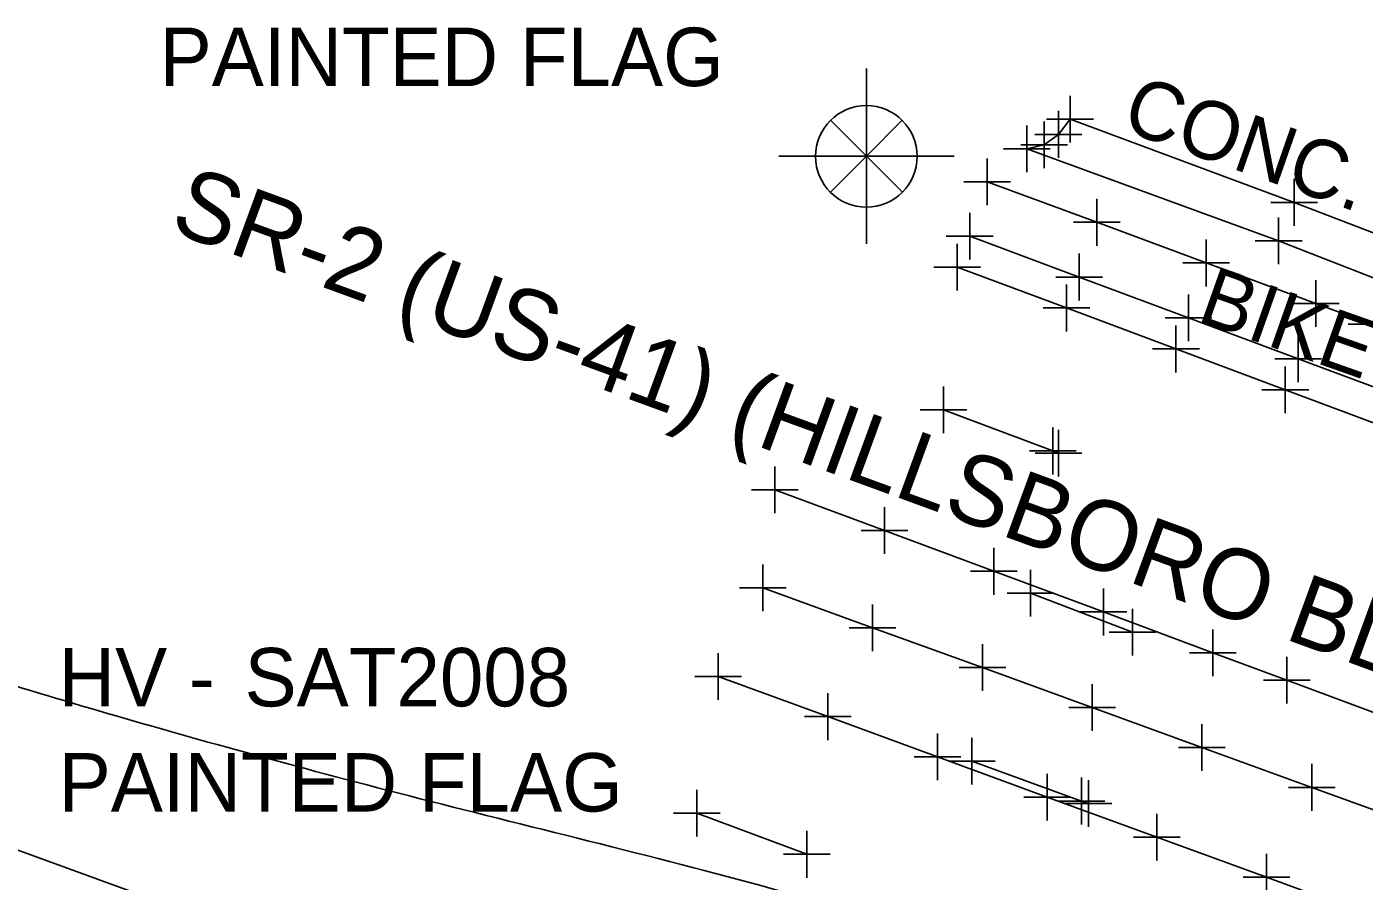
# Model space of a CAD drawing. Extents: x 0 to 1944463, y 0 to 420651.
# Drawn here: x 1942403.1 to 1942517.6, y 417930.2 to 418003.4 of the extents above; entities that cross this region are included whole.
import ezdxf

# ---------------------------------------------------------------- set-up
doc = ezdxf.new("R2010")
doc.units = 0
for name, color, linetype in [('AERIAL - CTRL - Points', 7, 'Continuous'), ('AERIAL - CTRL - Text', 7, 'Continuous'), ('SUR - DRG - Storm Sewer Text', 7, 'Continuous'), ('SUR - DTM - Breaklines', 7, 'Continuous'), ('SUR - DTM - Breaklines - Points - Locators', 7, 'Continuous'), ('SUR - TR-CTRL - Pavement Marking', 7, 'Continuous'), ('SUR - TR-CTRL - Pavement Marking - Points - Locators', 7, 'Continuous'), ('SUR - TRAN - Features', 7, 'Continuous'), ('SUR - TRAN - Features - Points - Locators', 7, 'Continuous'), ('SUR - TRAN - Features Text', 7, 'Continuous'), ('SUR - TRAN - Roads Text', 7, 'Continuous')]:
    doc.layers.add(name, color=color, linetype=linetype)

msp = doc.modelspace()

# ---------------------------------------------------------------- linework, layer by layer
at = {"layer": 'AERIAL - CTRL - Points'}
for p, q in [((1942474.94, 417992.29), (1942474.94, 417999.79)), ((1942474.94, 417992.29), (1942471.87, 417995.36)), ((1942474.94, 417992.29), (1942478.01, 417995.36)), ((1942467.44, 417992.29), (1942474.94, 417992.29)), ((1942471.86, 417989.21), (1942474.94, 417992.29)), ((1942474.94, 417992.29), (1942474.94, 417992.29)), ((1942474.94, 417992.29), (1942482.44, 417992.29)), ((1942478.03, 417989.21), (1942474.94, 417992.29)), ((1942474.94, 417984.79), (1942474.94, 417992.29))]:
    msp.add_line(p, q, dxfattribs=at)
msp.add_circle((1942474.94, 417992.27), 4.35, dxfattribs=at)
at = {"layer": 'SUR - DRG - Storm Sewer Text'}
msp.add_open_spline([(1942357.56, 417966.03), (1942368.77, 417953.91), (1942538.56, 417912.18), (1942553.38, 417877.57)], degree=2, dxfattribs=at)
at = {"layer": 'SUR - DTM - Breaklines'}
msp.add_lwpolyline([(1942466.07, 417955.35), (1942475.47, 417951.93), (1942484.87, 417948.52), (1942494.27, 417945.1), (1942503.66, 417941.68), (1942513.06, 417938.27), (1942522.46, 417934.85)], dxfattribs=at)
at = {"layer": 'SUR - DTM - Breaklines - Points - Locators'}
for p, q in [((1942466.07, 417955.35), (1942466.07, 417957.35)), ((1942466.07, 417955.35), (1942464.07, 417955.35)), ((1942466.07, 417955.35), (1942468.07, 417955.35)), ((1942466.07, 417955.35), (1942466.07, 417953.35)), ((1942475.47, 417951.93), (1942475.47, 417953.93)), ((1942475.47, 417951.93), (1942473.47, 417951.93)), ((1942475.47, 417951.93), (1942477.47, 417951.93)), ((1942475.47, 417951.93), (1942475.47, 417949.93)), ((1942484.87, 417948.52), (1942484.87, 417950.52)), ((1942484.87, 417948.52), (1942482.87, 417948.52)), ((1942484.87, 417948.52), (1942486.87, 417948.52)), ((1942484.87, 417948.52), (1942484.87, 417946.52)), ((1942494.27, 417945.1), (1942494.27, 417947.1)), ((1942494.27, 417945.1), (1942492.27, 417945.1)), ((1942494.27, 417945.1), (1942496.27, 417945.1)), ((1942494.27, 417945.1), (1942494.27, 417943.1)), ((1942503.66, 417941.68), (1942503.66, 417943.68)), ((1942503.66, 417941.68), (1942501.66, 417941.68)), ((1942503.66, 417941.68), (1942505.66, 417941.68)), ((1942503.66, 417941.68), (1942503.66, 417939.68)), ((1942513.06, 417938.27), (1942513.06, 417940.27)), ((1942513.06, 417938.27), (1942511.06, 417938.27)), ((1942513.06, 417938.27), (1942515.06, 417938.27)), ((1942513.06, 417938.27), (1942513.06, 417936.27))]:
    msp.add_line(p, q, dxfattribs=at)
at = {"layer": 'SUR - TR-CTRL - Pavement Marking'}
for points in [[(1942485.28, 417990.1), (1942494.66, 417986.63), (1942504.03, 417983.15), (1942513.41, 417979.68), (1942518.19, 417977.91), (1942527.57, 417974.44), (1942536.95, 417970.96), (1942546.32, 417967.49), (1942554.67, 417964.4), (1942564.05, 417960.92), (1942573.42, 417957.45), (1942582.8, 417953.98), (1942592.18, 417950.5), (1942601.04, 417947.22), (1942610.31, 417943.49), (1942615.47, 417941.42), (1942622.2, 417939.05), (1942629.46, 417936.74), (1942645.59, 417933.58)], [(1942482.7, 417982.8), (1942492.07, 417979.3), (1942501.44, 417975.79), (1942510.8, 417972.29), (1942520.17, 417968.79), (1942529.53, 417965.28), (1942538.9, 417961.78), (1942544.32, 417959.75), (1942553.68, 417956.25), (1942563.05, 417952.75), (1942572.42, 417949.24), (1942581.78, 417945.74), (1942591.15, 417942.24), (1942600.51, 417938.73), (1942609.88, 417935.23), (1942617.64, 417932.33)], [(1942481.55, 417970.58), (1942490.91, 417967.06), (1942491.39, 417966.88)], [(1942467.11, 417963.74), (1942476.48, 417960.25), (1942485.86, 417956.76), (1942495.23, 417953.28), (1942504.6, 417949.79), (1942510.92, 417947.44), (1942520.3, 417943.95)], [(1942488.99, 417954.88), (1942497.72, 417951.56)], [(1942462.25, 417947.75), (1942471.64, 417944.32), (1942481.03, 417940.88), (1942490.42, 417937.44), (1942499.81, 417934.01), (1942509.2, 417930.57), (1942518.59, 417927.13)], [(1942483.96, 417940.52), (1942493.36, 417937.1), (1942493.95, 417936.89)], [(1942460.42, 417936.05), (1942469.83, 417932.54)]]:
    msp.add_lwpolyline(points, dxfattribs=at)
at = {"layer": 'SUR - TR-CTRL - Pavement Marking - Points - Locators'}
for p, q in [((1942485.28, 417990.1), (1942485.28, 417992.1)), ((1942485.28, 417990.1), (1942483.28, 417990.1)), ((1942485.28, 417990.1), (1942487.28, 417990.1)), ((1942485.28, 417990.1), (1942485.28, 417988.1)), ((1942494.66, 417986.63), (1942494.66, 417988.63)), ((1942494.66, 417986.63), (1942492.66, 417986.63)), ((1942494.66, 417986.63), (1942496.66, 417986.63)), ((1942494.66, 417986.63), (1942494.66, 417984.63)), ((1942504.03, 417983.15), (1942504.03, 417985.15)), ((1942482.7, 417982.8), (1942482.7, 417984.8)), ((1942504.03, 417983.15), (1942502.03, 417983.15)), ((1942504.03, 417983.15), (1942506.03, 417983.15)), ((1942504.03, 417983.15), (1942504.03, 417981.15)), ((1942482.7, 417982.8), (1942480.7, 417982.8)), ((1942482.7, 417982.8), (1942484.7, 417982.8)), ((1942482.7, 417982.8), (1942482.7, 417980.8)), ((1942513.41, 417979.68), (1942513.41, 417981.68)), ((1942492.07, 417979.3), (1942492.07, 417981.3)), ((1942513.41, 417979.68), (1942511.41, 417979.68)), ((1942513.41, 417979.68), (1942515.41, 417979.68)), ((1942513.41, 417979.68), (1942513.41, 417977.68)), ((1942492.07, 417979.3), (1942490.07, 417979.3)), ((1942492.07, 417979.3), (1942494.07, 417979.3)), ((1942492.07, 417979.3), (1942492.07, 417977.3)), ((1942501.44, 417975.79), (1942501.44, 417977.79)), ((1942518.19, 417977.91), (1942516.19, 417977.91)), ((1942501.44, 417975.79), (1942499.44, 417975.79)), ((1942501.44, 417975.79), (1942503.44, 417975.79)), ((1942501.44, 417975.79), (1942501.44, 417973.79)), ((1942510.8, 417972.29), (1942510.8, 417974.29)), ((1942481.55, 417970.58), (1942481.55, 417972.58)), ((1942510.8, 417972.29), (1942508.8, 417972.29)), ((1942510.8, 417972.29), (1942512.8, 417972.29)), ((1942510.8, 417972.29), (1942510.8, 417970.29)), ((1942481.55, 417970.58), (1942479.55, 417970.58)), ((1942481.55, 417970.58), (1942483.55, 417970.58)), ((1942481.55, 417970.58), (1942481.55, 417968.58)), ((1942490.91, 417967.06), (1942490.91, 417969.06)), ((1942491.39, 417966.88), (1942491.39, 417968.88)), ((1942490.91, 417967.06), (1942488.91, 417967.06)), ((1942491.39, 417966.88), (1942489.39, 417966.88)), ((1942490.91, 417967.06), (1942492.91, 417967.06)), ((1942490.91, 417967.06), (1942490.91, 417965.06)), ((1942491.39, 417966.88), (1942493.39, 417966.88)), ((1942491.39, 417966.88), (1942491.39, 417964.88)), ((1942467.11, 417963.74), (1942467.11, 417965.74)), ((1942467.11, 417963.74), (1942465.11, 417963.74)), ((1942467.11, 417963.74), (1942469.11, 417963.74)), ((1942467.11, 417963.74), (1942467.11, 417961.74)), ((1942476.48, 417960.25), (1942476.48, 417962.25)), ((1942476.48, 417960.25), (1942474.48, 417960.25)), ((1942476.48, 417960.25), (1942478.48, 417960.25)), ((1942476.48, 417960.25), (1942476.48, 417958.25)), ((1942485.86, 417956.76), (1942485.86, 417958.76)), ((1942485.86, 417956.76), (1942483.86, 417956.76)), ((1942485.86, 417956.76), (1942487.86, 417956.76)), ((1942485.86, 417956.76), (1942485.86, 417954.76)), ((1942488.99, 417954.88), (1942488.99, 417956.88)), ((1942488.99, 417954.88), (1942486.99, 417954.88)), ((1942488.99, 417954.88), (1942490.99, 417954.88)), ((1942488.99, 417954.88), (1942488.99, 417952.88)), ((1942495.23, 417953.28), (1942495.23, 417955.28)), ((1942495.23, 417953.28), (1942493.23, 417953.28)), ((1942495.23, 417953.28), (1942497.23, 417953.28)), ((1942495.23, 417953.28), (1942495.23, 417951.28)), ((1942497.72, 417951.56), (1942497.72, 417953.56)), ((1942497.72, 417951.56), (1942495.72, 417951.56)), ((1942497.72, 417951.56), (1942499.72, 417951.56)), ((1942497.72, 417951.56), (1942497.72, 417949.56)), ((1942504.6, 417949.79), (1942504.6, 417951.79)), ((1942462.25, 417947.75), (1942462.25, 417949.75)), ((1942504.6, 417949.79), (1942502.6, 417949.79)), ((1942504.6, 417949.79), (1942506.6, 417949.79)), ((1942504.6, 417949.79), (1942504.6, 417947.79)), ((1942510.92, 417947.44), (1942510.92, 417949.44)), ((1942462.25, 417947.75), (1942460.25, 417947.75)), ((1942462.25, 417947.75), (1942464.25, 417947.75)), ((1942462.25, 417947.75), (1942462.25, 417945.75)), ((1942510.92, 417947.44), (1942508.92, 417947.44)), ((1942510.92, 417947.44), (1942512.92, 417947.44)), ((1942510.92, 417947.44), (1942510.92, 417945.44)), ((1942471.64, 417944.32), (1942471.64, 417946.32)), ((1942471.64, 417944.32), (1942469.64, 417944.32)), ((1942471.64, 417944.32), (1942473.64, 417944.32)), ((1942471.64, 417944.32), (1942471.64, 417942.32)), ((1942481.03, 417940.88), (1942481.03, 417942.88)), ((1942483.96, 417940.52), (1942483.96, 417942.52)), ((1942481.03, 417940.88), (1942479.03, 417940.88)), ((1942481.03, 417940.88), (1942483.03, 417940.88)), ((1942481.03, 417940.88), (1942481.03, 417938.88)), ((1942483.96, 417940.52), (1942481.96, 417940.52)), ((1942483.96, 417940.52), (1942485.96, 417940.52)), ((1942483.96, 417940.52), (1942483.96, 417938.52)), ((1942490.42, 417937.44), (1942490.42, 417939.44)), ((1942493.36, 417937.1), (1942493.36, 417939.1)), ((1942493.95, 417936.89), (1942493.95, 417938.89)), ((1942460.42, 417936.05), (1942460.42, 417938.05)), ((1942490.42, 417937.44), (1942488.42, 417937.44)), ((1942490.42, 417937.44), (1942492.42, 417937.44)), ((1942490.42, 417937.44), (1942490.42, 417935.44)), ((1942493.36, 417937.1), (1942491.36, 417937.1)), ((1942493.36, 417937.1), (1942495.36, 417937.1)), ((1942493.36, 417937.1), (1942493.36, 417935.1)), ((1942460.42, 417936.05), (1942458.42, 417936.05)), ((1942460.42, 417936.05), (1942462.42, 417936.05)), ((1942460.42, 417936.05), (1942460.42, 417934.05)), ((1942493.95, 417936.89), (1942491.95, 417936.89)), ((1942493.95, 417936.89), (1942495.95, 417936.89)), ((1942493.95, 417936.89), (1942493.95, 417934.89)), ((1942499.81, 417934.01), (1942499.81, 417936.01)), ((1942469.83, 417932.54), (1942469.83, 417934.54)), ((1942499.81, 417934.01), (1942497.81, 417934.01)), ((1942499.81, 417934.01), (1942501.81, 417934.01)), ((1942499.81, 417934.01), (1942499.81, 417932.01)), ((1942469.83, 417932.54), (1942467.83, 417932.54)), ((1942469.83, 417932.54), (1942471.83, 417932.54)), ((1942469.83, 417932.54), (1942469.83, 417930.54)), ((1942509.2, 417930.57), (1942509.2, 417932.57)), ((1942509.2, 417930.57), (1942507.2, 417930.57)), ((1942509.2, 417930.57), (1942511.2, 417930.57)), ((1942509.2, 417930.57), (1942509.2, 417928.57))]:
    msp.add_line(p, q, dxfattribs=at)
at = {"layer": 'SUR - TRAN - Features'}
for points in [[(1942530.76, 417977.1), (1942529.25, 417979.14), (1942528.81, 417981.71), (1942511.56, 417988.34), (1942492.37, 417995.47), (1942491.37, 417994.16), (1942490.15, 417993.26), (1942488.67, 417992.91), (1942510.23, 417985.05), (1942530.49, 417977.15)], [(1942483.78, 417985.45), (1942493.15, 417981.95), (1942502.52, 417978.45), (1942511.89, 417974.95), (1942521.26, 417971.46), (1942525.71, 417969.79), (1942535.08, 417966.29), (1942544.45, 417962.8), (1942553.82, 417959.3), (1942563.19, 417955.8), (1942564.66, 417955.25), (1942574.03, 417951.75), (1942583.4, 417948.25), (1942592.76, 417944.76), (1942602.13, 417941.26), (1942611.5, 417937.76), (1942618.47, 417935.16)], [(1942398.07, 417934.48), (1942398.71, 417933.71), (1942399.31, 417932.17), (1942399.2, 417930.32), (1942396.76, 417924.64), (1942436.93, 417909.73), (1942438.42, 417915.31), (1942439.31, 417916.77), (1942440.73, 417917.7), (1942443.47, 417917.9), (1942398.45, 417934.29)]]:
    msp.add_lwpolyline(points, dxfattribs=at)
at = {"layer": 'SUR - TRAN - Features - Points - Locators'}
for p, q in [((1942492.37, 417995.47), (1942492.37, 417997.47)), ((1942492.37, 417995.47), (1942490.37, 417995.47)), ((1942491.37, 417994.16), (1942491.37, 417996.16)), ((1942492.37, 417995.47), (1942494.37, 417995.47)), ((1942492.37, 417995.47), (1942492.37, 417993.47)), ((1942488.67, 417992.91), (1942488.67, 417994.91)), ((1942490.15, 417993.26), (1942490.15, 417995.26)), ((1942490.15, 417993.26), (1942488.15, 417993.26)), ((1942491.37, 417994.16), (1942489.37, 417994.16)), ((1942490.15, 417993.26), (1942492.15, 417993.26)), ((1942490.15, 417993.26), (1942490.15, 417991.26)), ((1942491.37, 417994.16), (1942493.37, 417994.16)), ((1942491.37, 417994.16), (1942491.37, 417992.16)), ((1942488.67, 417992.91), (1942486.67, 417992.91)), ((1942488.67, 417992.91), (1942490.67, 417992.91)), ((1942488.67, 417992.91), (1942488.67, 417990.91)), ((1942511.56, 417988.34), (1942511.56, 417990.34)), ((1942483.78, 417985.45), (1942483.78, 417987.45)), ((1942511.56, 417988.34), (1942509.56, 417988.34)), ((1942511.56, 417988.34), (1942513.56, 417988.34)), ((1942511.56, 417988.34), (1942511.56, 417986.34)), ((1942510.23, 417985.05), (1942510.23, 417987.05)), ((1942483.78, 417985.45), (1942481.78, 417985.45)), ((1942483.78, 417985.45), (1942485.78, 417985.45)), ((1942483.78, 417985.45), (1942483.78, 417983.45)), ((1942510.23, 417985.05), (1942508.23, 417985.05)), ((1942510.23, 417985.05), (1942512.23, 417985.05)), ((1942510.23, 417985.05), (1942510.23, 417983.05)), ((1942493.15, 417981.95), (1942493.15, 417983.95)), ((1942493.15, 417981.95), (1942491.15, 417981.95)), ((1942493.15, 417981.95), (1942495.15, 417981.95)), ((1942493.15, 417981.95), (1942493.15, 417979.95)), ((1942502.52, 417978.45), (1942502.52, 417980.45)), ((1942502.52, 417978.45), (1942500.52, 417978.45)), ((1942502.52, 417978.45), (1942504.52, 417978.45)), ((1942502.52, 417978.45), (1942502.52, 417976.45)), ((1942511.89, 417974.95), (1942511.89, 417976.95)), ((1942511.89, 417974.95), (1942509.89, 417974.95)), ((1942511.89, 417974.95), (1942513.89, 417974.95)), ((1942511.89, 417974.95), (1942511.89, 417972.95))]:
    msp.add_line(p, q, dxfattribs=at)

# ---------------------------------------------------------------- texts
at = {"layer": 'AERIAL - CTRL - Text'}
for s, p in [('PAINTED FLAG', (1942414.44, 417998.29)), ('HV - ', (1942405.8, 417945.2)), ('SAT2008', (1942421.71, 417945.2)), ('PAINTED FLAG', (1942405.8, 417936.2))]:
    msp.add_text(s, height=5, dxfattribs=at).set_placement(p)
at = {"layer": 'SUR - TRAN - Features Text'}
for s, rotation, p in [('CONC.', 340.7168, (1942496.62, 417994.59)), ('BIKE PATH (ASP)', 340.5491, (1942503.11, 417978.24))]:
    msp.add_text(s, height=5, rotation=rotation, dxfattribs=at).set_placement(p)
at = {"layer": 'SUR - TRAN - Roads Text'}
msp.add_text('SR-2 (US-41) (HILLSBORO BLVD.) (ASP.)', height=6, rotation=339.9127, dxfattribs=at).set_placement((1942415.12, 417985.94))

doc.saveas('drawing.dxf')
